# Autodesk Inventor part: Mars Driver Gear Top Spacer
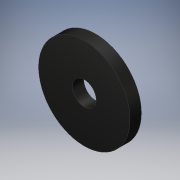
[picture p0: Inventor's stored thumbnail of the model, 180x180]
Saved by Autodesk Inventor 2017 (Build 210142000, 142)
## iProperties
Created: 2016-07
Part Number: Mars Driver Gear Top Spacer
Material: Generic
Document SubType Name: Modeling
Designer: Stan
Density: 1 g/cm^3
Appearance: Glossy - Black
Author: Stan
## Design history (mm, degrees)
sketch "Sketch1"
  geometry: C1 r 12.7 at (0, 0); C2 r 3.302 at (0, 0); 1 further point
  constraints: 2 centre point, 2 coincident
  dimensions: "d0" = 25.4 diameter of C1; "d1" = 6.604 diameter of C2
extrude "Extrusion1" new body sketch "Sketch1" distance "d2" = 3.175; taper "d3" = 0 deg
body "Solid1"
